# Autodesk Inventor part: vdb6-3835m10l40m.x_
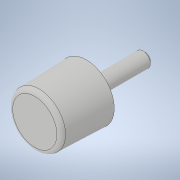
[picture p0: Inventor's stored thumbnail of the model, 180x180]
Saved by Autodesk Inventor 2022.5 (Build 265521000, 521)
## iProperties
Created: 2021-08
Part Number: vdb6-3835m10l40m.x_
Material: 一般
Document SubType Name: Modeling
Designer: ImaoCorp
Density: 1 g/cm^3
Appearance: 既定
Sending System: SOLIDWORKS 2019-2019304
MC: AMD64
MC_MODEL: Intel64 Family 6 Model 60 Stepping 3, GenuineIntel
OS: Windows_NT
FRU: Parasolid Version 31.0, build 290,  9- 1-2019
FORMAT: text
GUISE: transmit
KEY: vdb6-3835m10l40m
FILE: vdb6-3835m10l40m.x_t
DATE: Wed Aug 11 15:00:25 2021
Author: ImaoCorp
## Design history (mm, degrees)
feature "Base1"
node "ソリッド1"
